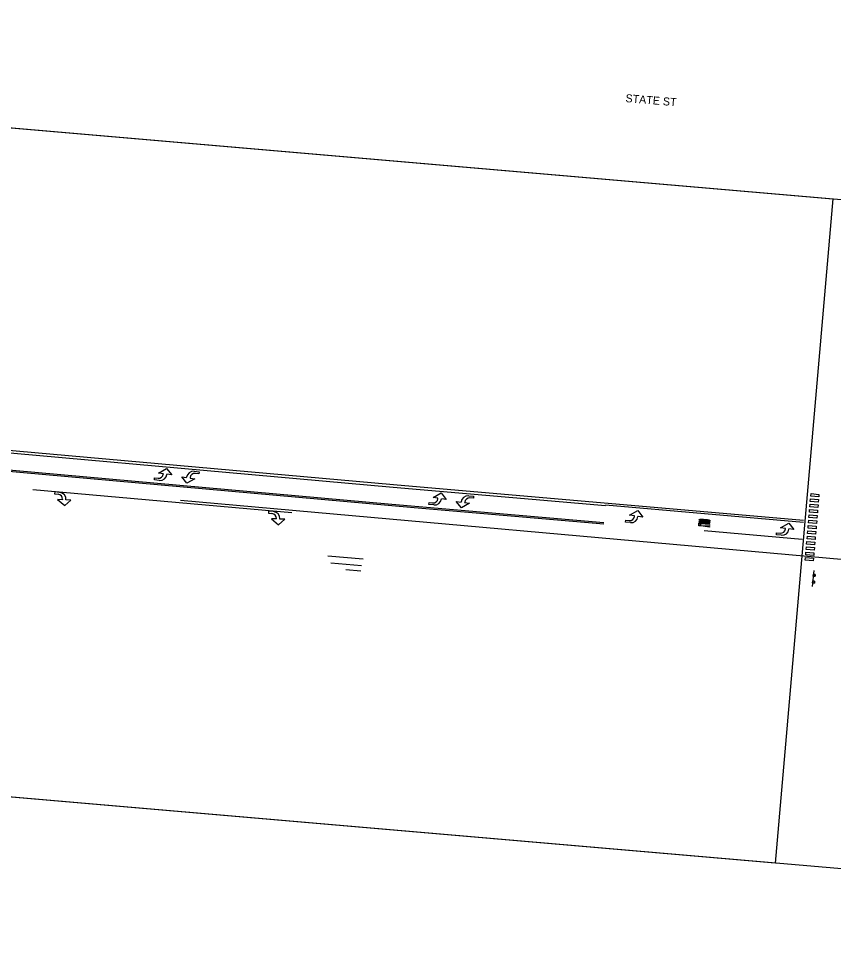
# Model space of a CAD drawing. Extents: x 20499978 to 20505524, y 7953342 to 7954320.
# Drawn here: x 20501922 to 20502533, y 7953512 to 7954213 of the extents above; entities that cross this region are included whole.
import ezdxf

# ---------------------------------------------------------------- set-up
doc = ezdxf.new("R2010")
doc.units = 0
for name, color, linetype in [('Curb', 7, 'Continuous'), ('EdgePaved', 7, 'Continuous'), ('Entrance', 7, 'Continuous'), ('Text', 7, 'Continuous'), ('trf_Cells1', 7, 'Continuous'), ('UtilitiesBelowGround', 7, 'Continuous')]:
    doc.layers.add(name, color=color, linetype=linetype)

msp = doc.modelspace()

# ---------------------------------------------------------------- linework, layer by layer
at = {"layer": 'Curb'}
msp.add_line((20502541.573650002, 7953806.8268784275), (20502043.561827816, 7953851.371518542), dxfattribs=at)
at = {"layer": 'EdgePaved'}
for p, q in [((20502203.260144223, 7953863.141575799), (20501795.92284754, 7953899.614667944)), ((20501794.540503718, 7953884.176432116), (20502218.73298789, 7953846.234943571)), ((20502510.72172472, 7953836.3568088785), (20502203.25834696, 7953863.141734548)), ((20501932.91246333, 7953859.738911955), (20502127.13543022, 7953842.348134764)), ((20502516.08993348, 7953854.544288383), (20502516.26338241, 7953856.537108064)), ((20502522.069279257, 7953854.023864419), (20502516.08993348, 7953854.544288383)), ((20502516.26338241, 7953856.537108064), (20502522.24281493, 7953856.016321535)), ((20502522.242814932, 7953856.016321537), (20502522.069279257, 7953854.023864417)), ((20502510.591552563, 7953834.862461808), (20502362.153811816, 7953847.79414624)), ((20502515.395790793, 7953846.574459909), (20502515.56923972, 7953848.56727959)), ((20502515.56923972, 7953848.56727959), (20502521.54867224, 7953848.046493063)), ((20502515.74286214, 7953850.559374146), (20502515.916311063, 7953852.552193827)), ((20502521.722207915, 7953850.0389501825), (20502515.74286214, 7953850.559374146)), ((20502515.916311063, 7953852.552193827), (20502521.895743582, 7953852.031407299)), ((20502521.548672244, 7953848.046493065), (20502521.37513657, 7953846.054035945)), ((20502521.895743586, 7953852.0314073), (20502521.722207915, 7953850.038950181)), ((20502218.73298789, 7953846.234943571), (20502360.93633647, 7953833.846781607)), ((20502514.701648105, 7953838.604631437), (20502514.875097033, 7953840.597451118)), ((20502514.875097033, 7953840.597451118), (20502520.854529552, 7953840.076664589)), ((20502515.04871945, 7953842.589545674), (20502515.222168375, 7953844.5823653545)), ((20502521.028065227, 7953842.069121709), (20502515.04871945, 7953842.589545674)), ((20502515.222168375, 7953844.5823653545), (20502521.201600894, 7953844.061578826)), ((20502521.37513657, 7953846.054035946), (20502515.395790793, 7953846.574459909)), ((20502521.201600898, 7953844.061578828), (20502521.028065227, 7953842.069121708)), ((20502514.367164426, 7953834.6336947), (20502514.540613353, 7953836.626514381)), ((20502520.3465102, 7953834.113270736), (20502514.367164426, 7953834.6336947)), ((20502514.540613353, 7953836.626514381), (20502520.520045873, 7953836.105727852)), ((20502520.68099388, 7953838.084207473), (20502514.701648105, 7953838.604631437)), ((20502520.520045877, 7953836.105727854), (20502520.3465102, 7953834.113270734)), ((20502520.854529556, 7953840.076664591), (20502520.68099388, 7953838.084207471)), ((20502436.061162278, 7953828.817965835), (20502509.507309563, 7953822.418704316)), ((20502513.673021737, 7953826.663866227), (20502513.846470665, 7953828.656685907)), ((20502519.652367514, 7953826.143442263), (20502513.673021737, 7953826.663866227)), ((20502513.846470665, 7953828.656685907), (20502519.825903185, 7953828.13589938)), ((20502514.020093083, 7953830.648780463), (20502514.193542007, 7953832.641600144)), ((20502519.99943886, 7953830.1283565), (20502514.020093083, 7953830.648780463)), ((20502514.193542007, 7953832.641600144), (20502520.172974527, 7953832.120813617)), ((20502519.82590319, 7953828.135899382), (20502519.652367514, 7953826.143442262)), ((20502520.17297453, 7953832.1208136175), (20502519.99943886, 7953830.128356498)), ((20502512.97887905, 7953818.694037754), (20502513.152327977, 7953820.686857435)), ((20502513.152327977, 7953820.686857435), (20502519.131760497, 7953820.166070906)), ((20502513.325950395, 7953822.678951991), (20502513.49939932, 7953824.671771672)), ((20502519.30529617, 7953822.158528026), (20502513.325950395, 7953822.678951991)), ((20502513.49939932, 7953824.671771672), (20502519.47883184, 7953824.150985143)), ((20502519.1317605, 7953820.166070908), (20502518.958224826, 7953818.173613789)), ((20502519.478831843, 7953824.150985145), (20502519.30529617, 7953822.158528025)), ((20502512.27345167, 7953810.725191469), (20502512.446900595, 7953812.71801115)), ((20502512.446900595, 7953812.71801115), (20502518.426333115, 7953812.197224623)), ((20502512.631807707, 7953814.709123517), (20502512.80525663, 7953816.701943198)), ((20502518.611153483, 7953814.188699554), (20502512.631807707, 7953814.709123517)), ((20502512.80525663, 7953816.701943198), (20502518.78468915, 7953816.181156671)), ((20502518.958224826, 7953818.17361379), (20502512.97887905, 7953818.694037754)), ((20502518.42633312, 7953812.1972246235), (20502518.252797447, 7953810.204767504)), ((20502518.784689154, 7953816.181156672), (20502518.611153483, 7953814.188699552)), ((20502180.407605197, 7953807.303058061), (20502154.078913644, 7953809.660536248)), ((20502511.926380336, 7953806.740277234), (20502512.09982926, 7953808.733096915)), ((20502517.905726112, 7953806.219853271), (20502511.926380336, 7953806.740277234)), ((20502512.09982926, 7953808.733096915), (20502518.07926178, 7953808.212310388)), ((20502518.252797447, 7953810.204767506), (20502512.27345167, 7953810.725191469)), ((20502518.079261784, 7953808.212310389), (20502517.905726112, 7953806.219853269)), ((20502179.24596157, 7953802.387068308), (20502156.368428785, 7953804.435528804)), ((20502178.88922768, 7953798.403007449), (20502167.450461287, 7953799.427237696))]:
    msp.add_line(p, q, dxfattribs=at)
for points in [[(20502362.114028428, 7953847.378971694), (20502203.09200555, 7953861.232306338), (20501795.75191305, 7953897.705645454)], [(20502361.001597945, 7953834.608532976), (20502201.961460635, 7953848.448849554), (20501794.60739132, 7953884.923443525)]]:
    msp.add_lwpolyline(points, dxfattribs=at)
at = {"layer": 'Entrance'}
for p, q in [((20502030.693985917, 7953871.201232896), (20502030.72125509, 7953871.514584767)), ((20502033.328324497, 7953871.1561547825), (20502033.31241748, 7953870.973366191)), ((20502048.14829281, 7953868.624665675), (20502048.16419983, 7953868.8074542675)), ((20502050.78263139, 7953868.579587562), (20502050.75536222, 7953868.2662356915)), ((20501955.12212247, 7953852.258818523), (20501955.09407104, 7953851.945535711)), ((20501957.72361363, 7953851.841666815), (20501957.739976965, 7953852.0244151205)), ((20502236.530056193, 7953852.770615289), (20502236.557325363, 7953853.0839671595)), ((20502239.164394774, 7953852.725537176), (20502239.148487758, 7953852.5427485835)), ((20502253.984363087, 7953850.194048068), (20502254.000270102, 7953850.37683666)), ((20502256.618701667, 7953850.148969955), (20502256.591432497, 7953849.835618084)), ((20502115.426347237, 7953837.871676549), (20502115.39829581, 7953837.558393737)), ((20502118.027838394, 7953837.454524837), (20502118.044201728, 7953837.637273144)), ((20502383.921866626, 7953839.521204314), (20502383.9491358, 7953839.834556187)), ((20502386.55620521, 7953839.476126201), (20502386.54029819, 7953839.29333761)), ((20502497.050845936, 7953830.080282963), (20502497.078115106, 7953830.393634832)), ((20502499.685184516, 7953830.035204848), (20502499.6692775, 7953829.852416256)), ((20502518.32632551, 7953798.830258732), (20502517.195622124, 7953786.88376042)), ((20502518.074075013, 7953796.165094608), (20502517.941910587, 7953794.768705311)), ((20502517.589472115, 7953791.045000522), (20502517.457307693, 7953789.648611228))]:
    msp.add_line(p, q, dxfattribs=at)
for points in [[(20502030.72125509, 7953871.514584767), (20502027.071357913, 7953872.0163867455), (20502033.177316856, 7953875.484203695)], [(20502030.72125509, 7953871.514584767), (20502027.071357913, 7953872.0163867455), (20502033.177316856, 7953875.484203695)], [(20502033.177316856, 7953875.484203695), (20502036.978221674, 7953870.654352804), (20502033.328324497, 7953871.1561547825)], [(20502033.177316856, 7953875.484203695), (20502036.978221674, 7953870.654352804), (20502033.328324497, 7953871.1561547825)], [(20502027.643792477, 7953866.467694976), (20502023.977988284, 7953866.786708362), (20502024.107516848, 7953868.275129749), (20502026.725948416, 7953868.047263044)], [(20502027.643792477, 7953866.467694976), (20502023.977988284, 7953866.786708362), (20502024.107516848, 7953868.275129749), (20502026.725948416, 7953868.047263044)], [(20502030.693985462, 7953871.201227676), (20502030.72125509, 7953871.514584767)], [(20502033.328324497, 7953871.1561547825), (20502033.31241747, 7953870.973366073)], [(20502048.299300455, 7953864.296616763), (20502044.498395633, 7953869.126467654), (20502048.14829281, 7953868.624665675)], [(20502048.299300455, 7953864.296616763), (20502044.498395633, 7953869.126467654), (20502048.14829281, 7953868.624665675)], [(20502048.14829281, 7953868.624665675), (20502048.16419984, 7953868.807454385)], [(20502050.75536222, 7953868.2662356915), (20502054.405259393, 7953867.764433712), (20502048.299300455, 7953864.296616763)], [(20502050.75536222, 7953868.2662356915), (20502054.405259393, 7953867.764433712), (20502048.299300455, 7953864.296616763)], [(20502050.782631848, 7953868.579592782), (20502050.75536222, 7953868.2662356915)], [(20502053.832824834, 7953873.313125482), (20502057.498629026, 7953872.994112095), (20502057.369100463, 7953871.505690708), (20502054.750668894, 7953871.733557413)], [(20502053.832824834, 7953873.313125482), (20502057.498629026, 7953872.994112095), (20502057.369100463, 7953871.505690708), (20502054.750668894, 7953871.733557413)], [(20501952.94841559, 7953857.453533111), (20501949.283419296, 7953857.781697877), (20501949.150175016, 7953856.293604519), (20501951.76802951, 7953856.0592011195)], [(20501952.94841559, 7953857.453533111), (20501949.283419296, 7953857.781697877), (20501949.150175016, 7953856.293604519), (20501951.76802951, 7953856.0592011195)], [(20502236.557325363, 7953853.0839671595), (20502232.90742819, 7953853.585769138), (20502239.013387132, 7953857.053586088)], [(20502236.557325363, 7953853.0839671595), (20502232.90742819, 7953853.585769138), (20502239.013387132, 7953857.053586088)], [(20502239.013387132, 7953857.053586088), (20502242.81429195, 7953852.2237351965), (20502239.164394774, 7953852.725537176)], [(20502239.013387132, 7953857.053586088), (20502242.81429195, 7953852.2237351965), (20502239.164394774, 7953852.725537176)], [(20502259.66889511, 7953854.882507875), (20502263.334699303, 7953854.563494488), (20502263.20517074, 7953853.075073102), (20502260.58673917, 7953853.302939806)], [(20502259.66889511, 7953854.882507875), (20502263.334699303, 7953854.563494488), (20502263.20517074, 7953853.075073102), (20502260.58673917, 7953853.302939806)], [(20501955.09407104, 7953851.945535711), (20501951.41271142, 7953852.090952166), (20501956.816673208, 7953847.607015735)], [(20501955.09407104, 7953851.945535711), (20501951.41271142, 7953852.090952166), (20501956.816673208, 7953847.607015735)], [(20501955.12212294, 7953852.258823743), (20501955.09407104, 7953851.945535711)], [(20501956.816673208, 7953847.607015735), (20501961.404973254, 7953851.696250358), (20501957.72361363, 7953851.841666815)], [(20501956.816673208, 7953847.607015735), (20501961.404973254, 7953851.696250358), (20501957.72361363, 7953851.841666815)], [(20501957.72361363, 7953851.841666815), (20501957.739976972, 7953852.02441524)], [(20502233.479862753, 7953848.037077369), (20502229.814058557, 7953848.356090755), (20502229.943587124, 7953849.844512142), (20502232.56201869, 7953849.616645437)], [(20502233.479862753, 7953848.037077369), (20502229.814058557, 7953848.356090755), (20502229.943587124, 7953849.844512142), (20502232.56201869, 7953849.616645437)], [(20502236.53005574, 7953852.770610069), (20502236.557325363, 7953853.0839671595)], [(20502239.164394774, 7953852.725537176), (20502239.148487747, 7953852.542748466)], [(20502254.135370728, 7953845.865999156), (20502250.33446591, 7953850.695850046), (20502253.984363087, 7953850.194048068)], [(20502254.135370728, 7953845.865999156), (20502250.33446591, 7953850.695850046), (20502253.984363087, 7953850.194048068)], [(20502253.984363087, 7953850.194048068), (20502254.000270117, 7953850.376836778)], [(20502256.591432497, 7953849.835618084), (20502260.24132967, 7953849.333816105), (20502254.135370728, 7953845.865999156)], [(20502256.591432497, 7953849.835618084), (20502260.24132967, 7953849.333816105), (20502254.135370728, 7953845.865999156)], [(20502256.61870212, 7953850.148975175), (20502256.591432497, 7953849.835618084)], [(20502113.252640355, 7953843.066391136), (20502109.587644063, 7953843.3945559), (20502109.454399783, 7953841.906462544), (20502112.072254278, 7953841.672059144)], [(20502113.252640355, 7953843.066391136), (20502109.587644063, 7953843.3945559), (20502109.454399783, 7953841.906462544), (20502112.072254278, 7953841.672059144)], [(20502383.9491358, 7953839.834556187), (20502380.299238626, 7953840.336358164), (20502386.40519757, 7953843.804175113)], [(20502383.9491358, 7953839.834556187), (20502380.299238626, 7953840.336358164), (20502386.40519757, 7953843.804175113)], [(20502386.40519757, 7953843.804175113), (20502390.206102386, 7953838.974324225), (20502386.55620521, 7953839.476126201)], [(20502386.40519757, 7953843.804175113), (20502390.206102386, 7953838.974324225), (20502386.55620521, 7953839.476126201)], [(20502115.39829581, 7953837.558393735), (20502111.71693619, 7953837.703810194), (20502117.12089798, 7953833.219873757)], [(20502115.39829581, 7953837.558393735), (20502111.71693619, 7953837.703810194), (20502117.12089798, 7953833.219873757)], [(20502115.426347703, 7953837.871681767), (20502115.39829581, 7953837.558393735)], [(20502117.12089798, 7953833.219873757), (20502121.709198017, 7953837.309108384), (20502118.027838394, 7953837.454524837)], [(20502117.12089798, 7953833.219873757), (20502121.709198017, 7953837.309108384), (20502118.027838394, 7953837.454524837)], [(20502118.027838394, 7953837.454524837), (20502118.04420174, 7953837.637273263)], [(20502380.871673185, 7953834.787666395), (20502377.205868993, 7953835.106679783), (20502377.335397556, 7953836.595101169), (20502379.95382912, 7953836.367234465)], [(20502380.871673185, 7953834.787666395), (20502377.205868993, 7953835.106679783), (20502377.335397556, 7953836.595101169), (20502379.95382912, 7953836.367234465)], [(20502383.921866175, 7953839.521199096), (20502383.9491358, 7953839.834556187)], [(20502386.55620521, 7953839.476126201), (20502386.54029818, 7953839.293337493)], [(20502497.078115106, 7953830.393634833), (20502493.42821793, 7953830.895436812), (20502499.534176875, 7953834.36325376)], [(20502497.078115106, 7953830.393634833), (20502493.42821793, 7953830.895436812), (20502499.534176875, 7953834.36325376)], [(20502499.534176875, 7953834.36325376), (20502503.33508169, 7953829.533402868), (20502499.685184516, 7953830.035204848)], [(20502499.534176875, 7953834.36325376), (20502503.33508169, 7953829.533402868), (20502499.685184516, 7953830.035204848)], [(20502494.000652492, 7953825.346745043), (20502490.3348483, 7953825.665758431), (20502490.464376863, 7953827.154179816), (20502493.08280843, 7953826.926313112)], [(20502494.000652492, 7953825.346745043), (20502490.3348483, 7953825.665758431), (20502490.464376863, 7953827.154179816), (20502493.08280843, 7953826.926313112)], [(20502497.050845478, 7953830.080277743), (20502497.078115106, 7953830.393634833)], [(20502499.685184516, 7953830.035204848), (20502499.669277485, 7953829.85241614)], [(20502517.941910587, 7953794.768705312), (20502519.338299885, 7953794.636540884), (20502519.470464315, 7953796.032930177), (20502518.07407502, 7953796.165094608)], [(20502517.457307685, 7953789.648611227), (20502518.85369699, 7953789.516446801), (20502518.985861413, 7953790.912836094), (20502517.58947212, 7953791.045000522)]]:
    msp.add_lwpolyline(points, dxfattribs=at)
for points in [[(20502517.941910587, 7953794.768705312), (20502518.07407502, 7953796.165094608), (20502519.470464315, 7953796.032930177), (20502519.338299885, 7953794.636540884)], [(20502517.457307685, 7953789.648611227), (20502517.58947212, 7953791.045000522), (20502518.985861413, 7953790.912836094), (20502518.85369699, 7953789.516446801)]]:
    msp.add_lwpolyline(points, close=True, dxfattribs=at)
for centre, major_axis, ratio, start_param, end_param in [((20502027.028181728, 7953871.520246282), (-3.665804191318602, 0.31901338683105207), 0.9474000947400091, 1.5707963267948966, 3.141592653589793), ((20502027.028181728, 7953871.520246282), (-3.665804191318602, 0.31901338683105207), 0.9474000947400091, 1.5707963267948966, 3.141592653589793), ((20502028.075554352, 7953871.429099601), (-5.236863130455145, 0.45573340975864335), 0.9474000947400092, 1.5707963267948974, 3.141592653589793), ((20502028.075554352, 7953871.429099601), (-5.236863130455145, 0.45573340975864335), 0.9474000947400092, 1.5707963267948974, 3.141592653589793), ((20502053.401062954, 7953868.3517208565), (5.236863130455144, -0.4557334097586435), 0.9474000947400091, 1.5707963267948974, 3.141592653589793), ((20502053.401062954, 7953868.3517208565), (5.236863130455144, -0.4557334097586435), 0.9474000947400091, 1.5707963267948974, 3.141592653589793), ((20502054.448435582, 7953868.260574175), (3.6658041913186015, -0.3190133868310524), 0.947400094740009, 1.5707963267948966, 3.141592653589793), ((20502054.448435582, 7953868.260574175), (3.6658041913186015, -0.3190133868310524), 0.947400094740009, 1.5707963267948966, 3.141592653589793), ((20501951.45712618, 7953852.586983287), (-3.6649962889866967, 0.3281647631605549), 0.9474000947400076, 3.141592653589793, 4.71238898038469), ((20501951.45712618, 7953852.586983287), (-3.6649962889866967, 0.3281647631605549), 0.9474000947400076, 3.141592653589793, 4.71238898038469), ((20501952.504267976, 7953852.4932219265), (-5.2357089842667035, 0.46880680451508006), 0.9474000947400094, 3.141592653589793, 4.712388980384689), ((20501952.504267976, 7953852.4932219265), (-5.2357089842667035, 0.46880680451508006), 0.9474000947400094, 3.141592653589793, 4.712388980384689), ((20502259.23713323, 7953849.921103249), (5.236863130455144, -0.4557334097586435), 0.9474000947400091, 1.5707963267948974, 3.141592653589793), ((20502259.23713323, 7953849.921103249), (5.236863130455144, -0.4557334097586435), 0.9474000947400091, 1.5707963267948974, 3.141592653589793), ((20502232.864252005, 7953853.089628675), (-3.665804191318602, 0.31901338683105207), 0.9474000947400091, 1.5707963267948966, 3.141592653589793), ((20502232.864252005, 7953853.089628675), (-3.665804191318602, 0.31901338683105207), 0.9474000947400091, 1.5707963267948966, 3.141592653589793), ((20502233.91162463, 7953852.998481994), (-5.236863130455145, 0.45573340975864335), 0.9474000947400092, 1.5707963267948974, 3.141592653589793), ((20502233.91162463, 7953852.998481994), (-5.236863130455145, 0.45573340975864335), 0.9474000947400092, 1.5707963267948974, 3.141592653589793), ((20502260.28450586, 7953849.829956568), (3.6658041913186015, -0.3190133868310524), 0.947400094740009, 1.5707963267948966, 3.141592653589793), ((20502260.28450586, 7953849.829956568), (3.6658041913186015, -0.3190133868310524), 0.947400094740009, 1.5707963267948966, 3.141592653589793), ((20502111.76135095, 7953838.199841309), (-3.6649962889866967, 0.3281647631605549), 0.9474000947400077, 3.141592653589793, 4.71238898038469), ((20502111.76135095, 7953838.199841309), (-3.6649962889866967, 0.3281647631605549), 0.9474000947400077, 3.141592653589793, 4.71238898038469), ((20502112.808492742, 7953838.106079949), (-5.2357089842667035, 0.46880680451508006), 0.9474000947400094, 3.141592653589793, 4.712388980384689), ((20502112.808492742, 7953838.106079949), (-5.2357089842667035, 0.46880680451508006), 0.9474000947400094, 3.141592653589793, 4.712388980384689), ((20502380.25606244, 7953839.840217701), (-3.6658041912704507, 0.3190133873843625), 0.9474000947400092, 1.5707963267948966, 3.141592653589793), ((20502380.25606244, 7953839.840217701), (-3.6658041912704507, 0.3190133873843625), 0.9474000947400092, 1.5707963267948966, 3.141592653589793), ((20502381.303435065, 7953839.749071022), (-5.236863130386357, 0.45573341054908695), 0.9474000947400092, 1.5707963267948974, 3.141592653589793), ((20502381.303435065, 7953839.749071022), (-5.236863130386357, 0.45573341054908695), 0.9474000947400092, 1.5707963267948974, 3.141592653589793), ((20502493.385041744, 7953830.399296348), (-3.6658041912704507, 0.3190133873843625), 0.9474000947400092, 1.5707963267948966, 3.141592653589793), ((20502493.385041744, 7953830.399296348), (-3.6658041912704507, 0.3190133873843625), 0.9474000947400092, 1.5707963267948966, 3.141592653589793), ((20502494.432414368, 7953830.308149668), (-5.236863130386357, 0.45573341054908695), 0.9474000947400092, 1.5707963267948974, 3.141592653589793), ((20502494.432414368, 7953830.308149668), (-5.236863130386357, 0.45573341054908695), 0.9474000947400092, 1.5707963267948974, 3.141592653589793)]:
    msp.add_ellipse(centre, major_axis=major_axis, ratio=ratio, start_param=start_param, end_param=end_param, dxfattribs=at)
at = {"layer": 'Text'}
for points in [[(20500970.870100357, 7954212.672987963), (20502532.504970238, 7954077.5622130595), (20502489.40637099, 7953579.420777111), (20500927.771501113, 7953714.531552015)], [(20501752.189117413, 7954145.122862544), (20503313.82398729, 7954010.012087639), (20503270.725388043, 7953511.870651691), (20501709.090518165, 7953646.981426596)]]:
    msp.add_lwpolyline(points, close=True, dxfattribs=at)
at = {"layer": 'trf_Cells1'}
for p, q in [((20502437.217732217, 7953835.894348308), (20502435.623275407, 7953836.027410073)), ((20502435.64988776, 7953836.3463014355), (20502437.24434457, 7953836.2132396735)), ((20502437.297569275, 7953836.851022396), (20502435.703112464, 7953836.984084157)), ((20502435.729724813, 7953837.30297552), (20502437.324181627, 7953837.1699137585))]:
    msp.add_line(p, q, dxfattribs=at)
for points in [[(20502432.274310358, 7953834.375664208), (20502440.246594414, 7953833.710355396), (20502440.21998206, 7953833.391464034), (20502433.52326346, 7953833.950323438), (20502433.4434264, 7953832.9936493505), (20502432.16786095, 7953833.10009876)], [(20502432.40737213, 7953835.970121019), (20502440.379656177, 7953835.304812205), (20502440.353043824, 7953834.985920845), (20502435.197557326, 7953834.773935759), (20502440.29981912, 7953834.34813812), (20502440.273206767, 7953834.029246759), (20502432.300922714, 7953834.69455557), (20502432.32753507, 7953835.013446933), (20502437.48302156, 7953835.225432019), (20502432.38075977, 7953835.651229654)], [(20502440.15345118, 7953832.594235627), (20502440.126838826, 7953832.275344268), (20502436.911312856, 7953832.222576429), (20502440.07361412, 7953831.637561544), (20502440.047001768, 7953831.318670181), (20502435.30354987, 7953832.196192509), (20502432.11463625, 7953832.462316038), (20502432.1412486, 7953832.7812073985), (20502435.33016222, 7953832.515083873)]]:
    msp.add_lwpolyline(points, close=True, dxfattribs=at)
for points in [[(20502435.623275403, 7953836.02741007), (20502435.424768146, 7953836.0464909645), (20502435.127840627, 7953836.072277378), (20502434.95158518, 7953836.096049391), (20502434.73891113, 7953836.11782562), (20502434.597573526, 7953836.137676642), (20502434.432485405, 7953836.162530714), (20502434.300231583, 7953836.182630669), (20502434.146310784, 7953836.208566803), (20502433.94163846, 7953836.241759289), (20502433.844636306, 7953836.261938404), (20502433.747383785, 7953836.279117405), (20502433.618630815, 7953836.304967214), (20502433.47696082, 7953836.332901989), (20502433.34095866, 7953836.368419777), (20502433.206206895, 7953836.40685422), (20502433.085455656, 7953836.444120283), (20502432.958288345, 7953836.488970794), (20502432.812038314, 7953836.546490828), (20502432.684540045, 7953836.6115089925), (20502432.593792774, 7953836.670439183), (20502432.53746405, 7953836.731532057), (20502432.51163573, 7953836.784037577), (20502432.494307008, 7953836.82979178), (20502432.48631244, 7953836.878795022), (20502432.48758649, 7953836.931316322)], [(20502432.48758649, 7953836.931316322), (20502432.49503553, 7953836.9833223), (20502432.51104185, 7953837.030322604), (20502432.535714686, 7953837.072571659), (20502432.56988858, 7953837.120069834), (20502432.635564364, 7953837.170981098), (20502432.73482412, 7953837.214054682), (20502432.871335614, 7953837.257040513), (20502433.025096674, 7953837.289523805), (20502433.157938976, 7953837.312675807), (20502433.28319683, 7953837.329411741), (20502433.422455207, 7953837.344979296), (20502433.562463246, 7953837.357463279), (20502433.706803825, 7953837.361529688), (20502433.838060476, 7953837.36568099), (20502433.9368152, 7953837.366502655), (20502434.035820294, 7953837.370324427), (20502434.243163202, 7953837.369133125), (20502434.399253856, 7953837.369197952), (20502434.53300988, 7953837.367098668), (20502434.699934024, 7953837.364245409), (20502434.842606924, 7953837.360394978), (20502435.055948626, 7953837.346619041), (20502435.233706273, 7953837.340847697), (20502435.53080071, 7953837.317061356), (20502435.729724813, 7953837.30297552)], [(20502435.703112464, 7953836.984084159), (20502435.548346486, 7953836.993356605), (20502435.31967077, 7953837.0074052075), (20502435.014741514, 7953837.021775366), (20502434.747563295, 7953837.029974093), (20502434.49396832, 7953837.032004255), (20502434.28562466, 7953837.027237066), (20502434.10878073, 7953837.007757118), (20502433.947436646, 7953836.980941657), (20502433.856262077, 7953836.9502843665), (20502433.791753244, 7953836.901289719), (20502433.763151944, 7953836.82486691)], [(20502433.763151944, 7953836.82486691), (20502433.778690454, 7953836.744760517), (20502433.83418606, 7953836.685751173), (20502433.919017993, 7953836.640405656), (20502434.073685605, 7953836.587218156), (20502434.244854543, 7953836.5386955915), (20502434.44952615, 7953836.499461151), (20502434.699949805, 7953836.459429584), (20502434.96479126, 7953836.423229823), (20502435.26788448, 7953836.386858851), (20502435.495725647, 7953836.362809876), (20502435.64988776, 7953836.346301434)], [(20502440.459870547, 7953836.266007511), (20502440.452421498, 7953836.214001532), (20502440.436415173, 7953836.167001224), (20502440.411742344, 7953836.124752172), (20502440.37756845, 7953836.077253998), (20502440.311892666, 7953836.026342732), (20502440.212632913, 7953835.983269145), (20502440.076121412, 7953835.940283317), (20502439.922360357, 7953835.9078000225), (20502439.78951805, 7953835.88464802), (20502439.664260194, 7953835.8679120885), (20502439.525001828, 7953835.852344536), (20502439.38499378, 7953835.839860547), (20502439.2406532, 7953835.835794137), (20502439.10939656, 7953835.831642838), (20502439.010641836, 7953835.830821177), (20502438.91163674, 7953835.826999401), (20502438.704293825, 7953835.828190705), (20502438.54820317, 7953835.828125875), (20502438.414447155, 7953835.830225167), (20502438.247523, 7953835.833078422), (20502438.104850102, 7953835.836928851), (20502437.891508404, 7953835.850704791), (20502437.713750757, 7953835.8564761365), (20502437.41665632, 7953835.880262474), (20502437.217732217, 7953835.89434831)], [(20502437.24434457, 7953836.2132396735), (20502437.39911054, 7953836.203967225), (20502437.627786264, 7953836.189918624), (20502437.932715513, 7953836.175548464), (20502438.19989373, 7953836.167349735), (20502438.45348871, 7953836.165319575), (20502438.66183237, 7953836.170086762), (20502438.838676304, 7953836.189566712), (20502439.000020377, 7953836.216382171), (20502439.091194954, 7953836.247039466), (20502439.155703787, 7953836.296034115), (20502439.184305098, 7953836.37245692)], [(20502439.184305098, 7953836.37245692), (20502439.168766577, 7953836.452563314), (20502439.11327097, 7953836.511572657), (20502439.028439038, 7953836.556918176), (20502438.873771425, 7953836.610105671), (20502438.70260249, 7953836.658628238), (20502438.49793088, 7953836.697862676), (20502438.247507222, 7953836.737894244), (20502437.982665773, 7953836.774094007), (20502437.679572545, 7953836.810464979), (20502437.45173138, 7953836.834513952), (20502437.297569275, 7953836.851022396)], [(20502437.324181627, 7953837.169913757), (20502437.52268888, 7953837.150832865), (20502437.819616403, 7953837.125046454), (20502437.995871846, 7953837.101274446), (20502438.208545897, 7953837.079498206), (20502438.349883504, 7953837.059647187), (20502438.51497163, 7953837.034793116), (20502438.64722544, 7953837.014693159), (20502438.801146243, 7953836.988757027), (20502439.005818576, 7953836.955564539), (20502439.102820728, 7953836.935385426), (20502439.200073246, 7953836.918206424), (20502439.328826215, 7953836.8923566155), (20502439.47049621, 7953836.864421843), (20502439.60649838, 7953836.828904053), (20502439.74125013, 7953836.79046961), (20502439.862001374, 7953836.7532035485), (20502439.989168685, 7953836.708353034), (20502440.135418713, 7953836.6508329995), (20502440.262916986, 7953836.5858148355), (20502440.353664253, 7953836.526884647), (20502440.409992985, 7953836.465791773), (20502440.435821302, 7953836.413286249), (20502440.453150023, 7953836.367532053), (20502440.46114459, 7953836.318528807), (20502440.459870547, 7953836.266007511)]]:
    msp.add_spline(points, degree=3, dxfattribs=at)

# ---------------------------------------------------------------- texts
at = {"layer": 'UtilitiesBelowGround'}
msp.add_text('STATE ST', height=5.999999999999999, rotation=355.27334336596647, dxfattribs=at).set_placement((20502376.99246376, 7954150.158806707))

doc.saveas('drawing.dxf')
